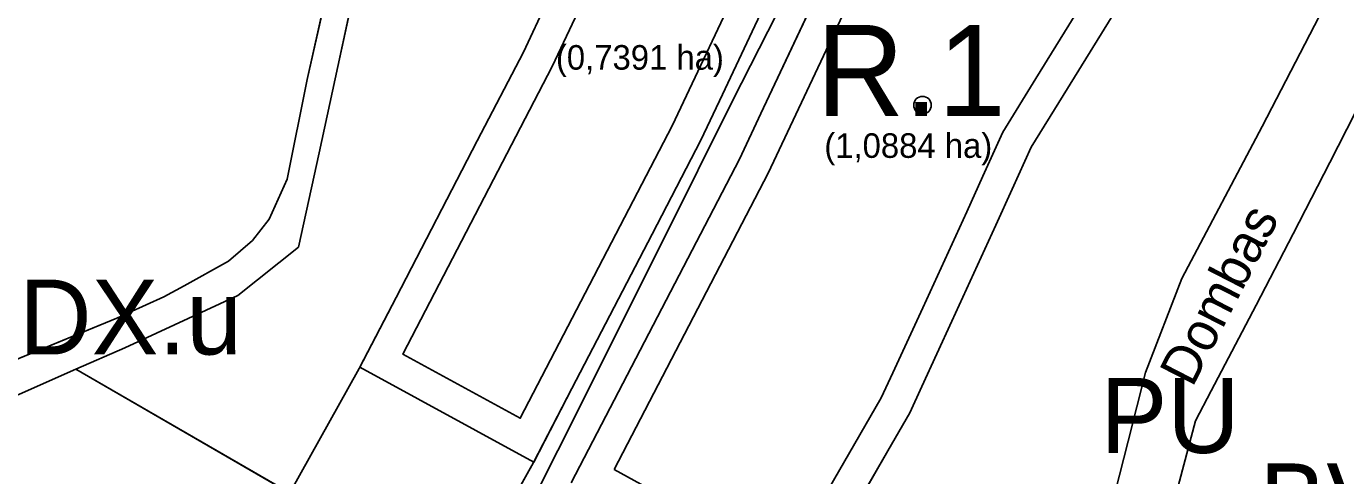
# Model space of a CAD drawing. Extents: x -555509 to -553005, y -1186756 to -1182560.
# Drawn here: x -554876.1 to -554629.7, y -1185321 to -1185237.1 of the extents above; entities that cross this region are included whole.
import ezdxf

# ---------------------------------------------------------------- set-up
doc = ezdxf.new("R2010")
doc.units = 0
for name, color, linetype in [('Level 15', 7, 'Continuous'), ('Level 26', 7, 'Continuous'), ('Level 29', 7, 'Continuous'), ('Level 36', 7, 'Continuous'), ('Level 4', 7, 'Continuous'), ('Level 46', 7, 'Continuous'), ('Level 52', 7, 'Continuous'), ('Level 56', 7, 'Continuous'), ('Level 57', 7, 'Continuous'), ('Level 59', 7, 'Continuous'), ('Level 6', 7, 'Continuous'), ('navrh_BV', 7, 'Continuous'), ('OBRYS_PLOCH', 7, 'Continuous'), ('rezerva_BV', 7, 'Continuous'), ('stav_AP', 7, 'Continuous'), ('stav_BV', 7, 'Continuous'), ('stav_PU', 7, 'Continuous'), ('stav_ZZ', 7, 'Continuous')]:
    doc.layers.add(name, color=color, linetype=linetype)

msp = doc.modelspace()

# ---------------------------------------------------------------- linework, layer by layer
at = {"layer": 'Level 15'}
for p, q in [((-554736.11, -1185228.65), (-554746.09, -1185249.82)), ((-554744.13, -1185250.86), (-554733.51, -1185230.02)), ((-554746.09, -1185249.82), (-554750.09, -1185258.31)), ((-554757.18, -1185276.99), (-554744.13, -1185250.86)), ((-554750.09, -1185258.31), (-554759.23, -1185275.9)), ((-554759.23, -1185275.9), (-554774.2, -1185304.73)), ((-554771.69, -1185306.03), (-554757.18, -1185276.99)), ((-554791.22, -1185344.83), (-554771.69, -1185306.03))]:
    msp.add_line(p, q, dxfattribs=at)
for points in [[(-554598.76, -1185166.79), (-554607.1, -1185184.92), (-554613.87, -1185198.73), (-554631.94, -1185230), (-554645.24, -1185255.79), (-554660.25, -1185284.19), (-554660.25, -1185284.19)], [(-554680.05, -1185391.93), (-554677.6, -1185383.35), (-554671.14, -1185360.64), (-554665.38, -1185339.39), (-554660.73, -1185322.02), (-554657.69, -1185310.75), (-554654.76, -1185305.13), (-554646.4, -1185289.14), (-554639.48, -1185275.83), (-554632.63, -1185262.48), (-554627.88, -1185253.22), (-554621, -1185239.68)], [(-554660.25, -1185284.19), (-554667.06, -1185301.73)], [(-554667.06, -1185301.73), (-554670.31, -1185314.54)], [(-554774.2, -1185304.73), (-554781.36, -1185318.51), (-554794.88, -1185342.72)], [(-554670.31, -1185314.54), (-554673.54, -1185327.25), (-554676.78, -1185340.05), (-554680, -1185352.72), (-554683.21, -1185365.38), (-554687.71, -1185383.13)]]:
    msp.add_lwpolyline(points, dxfattribs=at)
at = {"layer": 'Level 26'}
msp.add_line((-554817.98, -1185221.63), (-554823.63, -1185247), dxfattribs=at)
for points in [[(-554887.99, -1185310.44), (-554866.85, -1185301.12), (-554857.71, -1185297.09), (-554836.62, -1185287.33), (-554825.26, -1185278.31), (-554821.43, -1185260.7), (-554817.93, -1185244.58), (-554811.52, -1185215.05), (-554805.21, -1185192.12), (-554804.77, -1185189.6), (-554803.27, -1185184.93), (-554798.69, -1185167.93), (-554796.09, -1185156.74), (-554793.47, -1185148.48), (-554787.3, -1185127.39), (-554786.27, -1185123.73), (-554781.87, -1185108.14), (-554781.11, -1185105.46), (-554780.74, -1185090.36), (-554781.66, -1185076.22)], [(-554823.63, -1185247), (-554827.41, -1185265.63), (-554830.77, -1185273.06), (-554833.85, -1185277.07), (-554838.37, -1185280.92), (-554846.66, -1185285.51), (-554850.4, -1185287.59), (-554857.04, -1185290.6), (-554859.24, -1185291.6), (-554887.1, -1185303.03), (-554901.81, -1185309.08), (-554916.01, -1185314.9), (-554918.93, -1185316.1), (-554926.41, -1185318.46), (-554942.11, -1185323.84), (-554945.03, -1185324.82), (-554968.06, -1185330.5), (-554985.17, -1185335.34), (-555017.36, -1185344.44), (-555025.25, -1185346.9), (-555037.24, -1185350.65)]]:
    msp.add_lwpolyline(points, dxfattribs=at)
at = {"layer": 'Level 36'}
for p, q in [((-554791.87, -1185258.48), (-554807.06, -1185287.73)), ((-554807.06, -1185287.73), (-554813.94, -1185300.96)), ((-554813.94, -1185300.96), (-554826.92, -1185324.2))]:
    msp.add_line(p, q, dxfattribs=at)
msp.add_lwpolyline([(-554778.8, -1185232.44), (-554783.25, -1185241.89), (-554791.87, -1185258.48)], dxfattribs=at)
at = {"layer": 'Level 4'}
msp.add_circle((-554708.72, -1185251.8), 1.64, dxfattribs=at)
at = {"layer": 'Level 52'}
for points in [[(-554651.54, -1185198.32), (-554660.04, -1185213.75), (-554661.31, -1185215.81), (-554671.87, -1185232.89), (-554682.43, -1185249.97), (-554688.42, -1185259.67), (-554691.95, -1185267.5), (-554694.99, -1185274.23)], [(-554694.99, -1185274.23), (-554703.22, -1185292.14), (-554708.82, -1185304.31), (-554711.08, -1185309.23), (-554715.19, -1185316.37), (-554721.98, -1185328.15)]]:
    msp.add_lwpolyline(points, dxfattribs=at)
at = {"layer": 'Level 56'}
for p, q in [((-554813.94, -1185300.96), (-554826.92, -1185324.2)), ((-554813.83, -1185300.75), (-554813.94, -1185300.96)), ((-554781.34, -1185318.48), (-554813.83, -1185300.75))]:
    msp.add_line(p, q, dxfattribs=at)
msp.add_lwpolyline([(-554794.88, -1185342.72), (-554781.36, -1185318.51), (-554781.34, -1185318.48)], dxfattribs=at)
at = {"layer": 'Level 6'}
for points in [[(-554651.54, -1185198.32), (-554660.04, -1185213.75), (-554661.31, -1185215.81), (-554671.87, -1185232.89), (-554682.43, -1185249.97), (-554688.42, -1185259.67), (-554691.95, -1185267.5), (-554694.99, -1185274.23)], [(-554694.99, -1185274.23), (-554703.22, -1185292.14), (-554708.82, -1185304.31), (-554711.08, -1185309.23), (-554715.19, -1185316.37), (-554721.98, -1185328.15)]]:
    msp.add_lwpolyline(points, dxfattribs=at)
at = {"layer": 'navrh_BV'}
for p, q in [((-554813.94, -1185300.96), (-554826.92, -1185324.2)), ((-554813.94, -1185300.96), (-554826.92, -1185324.2)), ((-554813.83, -1185300.75), (-554813.94, -1185300.96)), ((-554813.83, -1185300.75), (-554813.94, -1185300.96)), ((-554781.34, -1185318.48), (-554813.83, -1185300.75)), ((-554781.34, -1185318.48), (-554813.83, -1185300.75)), ((-554794.88, -1185342.72), (-554781.36, -1185318.51)), ((-554794.88, -1185342.72), (-554781.36, -1185318.51)), ((-554781.36, -1185318.51), (-554781.34, -1185318.48)), ((-554781.36, -1185318.51), (-554781.34, -1185318.48))]:
    msp.add_line(p, q, dxfattribs=at)
at = {"layer": 'OBRYS_PLOCH'}
for p, q in [((-554811.52, -1185215.05), (-554817.93, -1185244.58)), ((-554817.98, -1185221.63), (-554823.63, -1185247)), ((-554736.11, -1185228.65), (-554746.09, -1185249.82)), ((-554671.87, -1185232.89), (-554682.43, -1185249.97)), ((-554817.93, -1185244.58), (-554821.43, -1185260.7)), ((-554682.43, -1185249.97), (-554688.42, -1185259.67)), ((-554742.92, -1185261.86), (-554738.91, -1185253.34)), ((-554821.43, -1185260.7), (-554825.26, -1185278.31)), ((-554807.06, -1185287.73), (-554791.87, -1185258.48)), ((-554688.42, -1185259.67), (-554691.95, -1185267.5)), ((-554774.32, -1185322.31), (-554742.92, -1185261.86)), ((-554691.95, -1185267.5), (-554694.99, -1185274.23)), ((-554759.23, -1185275.9), (-554774.2, -1185304.73)), ((-554825.26, -1185278.31), (-554836.62, -1185287.33)), ((-554836.62, -1185287.33), (-554857.71, -1185297.09)), ((-554813.94, -1185300.96), (-554807.06, -1185287.73)), ((-554857.71, -1185297.09), (-554866.85, -1185301.12)), ((-554866.85, -1185301.12), (-554826.92, -1185324.2)), ((-554826.92, -1185324.2), (-554813.94, -1185300.96)), ((-554813.94, -1185300.96), (-554826.92, -1185324.2)), ((-554813.83, -1185300.75), (-554813.94, -1185300.96)), ((-554781.34, -1185318.48), (-554813.83, -1185300.75)), ((-554774.2, -1185304.73), (-554781.36, -1185318.51)), ((-554781.36, -1185318.51), (-554794.88, -1185342.72)), ((-554794.88, -1185342.72), (-554781.36, -1185318.51)), ((-554781.36, -1185318.51), (-554781.34, -1185318.48))]:
    msp.add_line(p, q, dxfattribs=at)
for points in [[(-554887.99, -1185310.44), (-554866.85, -1185301.12), (-554857.71, -1185297.09), (-554836.62, -1185287.33), (-554825.26, -1185278.31), (-554821.43, -1185260.7), (-554817.93, -1185244.58), (-554811.52, -1185215.05), (-554805.21, -1185192.12), (-554804.77, -1185189.6), (-554803.27, -1185184.93), (-554798.69, -1185167.93), (-554796.09, -1185156.74), (-554793.47, -1185148.48), (-554787.3, -1185127.39), (-554786.27, -1185123.73), (-554781.87, -1185108.14), (-554781.11, -1185105.46), (-554780.74, -1185090.36), (-554781.66, -1185076.22)], [(-554738.91, -1185253.34), (-554709.98, -1185191.97), (-554688.49, -1185135.67)], [(-554887.1, -1185303.03), (-554859.24, -1185291.6), (-554857.04, -1185290.6), (-554850.4, -1185287.59), (-554846.66, -1185285.51), (-554838.37, -1185280.92), (-554833.85, -1185277.07), (-554830.77, -1185273.06), (-554827.41, -1185265.63), (-554823.63, -1185247), (-554817.98, -1185221.63), (-554810.95, -1185192.05), (-554810.27, -1185189.91), (-554835.6, -1185178.86), (-554845.02, -1185174.75), (-554857.62, -1185169.14), (-554867.48, -1185164.75), (-554870.22, -1185163.53), (-554877.3, -1185160.22)], [(-554660.25, -1185284.19), (-554645.24, -1185255.79), (-554631.94, -1185230), (-554613.87, -1185198.73), (-554607.1, -1185184.92), (-554598.76, -1185166.79)], [(-554791.87, -1185258.48), (-554783.25, -1185241.89), (-554778.8, -1185232.44)], [(-554588.35, -1185339.59), (-554594.02, -1185336.6), (-554595.16, -1185336), (-554581.44, -1185321.01), (-554582.54, -1185305.03), (-554583.52, -1185290.79), (-554585.87, -1185256.63), (-554586.41, -1185249.88), (-554586.6, -1185246.65), (-554587.16, -1185237.33), (-554607.25, -1185238.73), (-554621, -1185239.68), (-554627.88, -1185253.22), (-554632.63, -1185262.48), (-554639.48, -1185275.83), (-554646.4, -1185289.14), (-554654.76, -1185305.13), (-554657.69, -1185310.75), (-554660.73, -1185322.02), (-554665.38, -1185339.39), (-554671.14, -1185360.64), (-554677.6, -1185383.35), (-554680.05, -1185391.93)], [(-554823.63, -1185247), (-554827.41, -1185265.63), (-554830.77, -1185273.06), (-554833.85, -1185277.07), (-554838.37, -1185280.92), (-554846.66, -1185285.51), (-554850.4, -1185287.59), (-554857.04, -1185290.6), (-554859.24, -1185291.6), (-554887.1, -1185303.03), (-554901.81, -1185309.08), (-554916.01, -1185314.9), (-554918.93, -1185316.1), (-554926.41, -1185318.46), (-554942.11, -1185323.84), (-554945.03, -1185324.82), (-554968.06, -1185330.5), (-554985.17, -1185335.34), (-555017.36, -1185344.44), (-555025.25, -1185346.9), (-555037.24, -1185350.65)], [(-554746.09, -1185249.82), (-554750.09, -1185258.31), (-554759.23, -1185275.9)], [(-554694.99, -1185274.23), (-554703.22, -1185292.14), (-554708.82, -1185304.31), (-554711.08, -1185309.23), (-554715.19, -1185316.37), (-554721.98, -1185328.15), (-554728.42, -1185339.33), (-554731.79, -1185345.18), (-554734.88, -1185350.42), (-554742.18, -1185362.81), (-554744.55, -1185366.82), (-554747.05, -1185371.06), (-554752.81, -1185380.83), (-554760.45, -1185393.79), (-554768.14, -1185406.83), (-554772.69, -1185415.93)], [(-554761.09, -1185439.66), (-554755.74, -1185436.95), (-554734.36, -1185426.09), (-554706.82, -1185409.97), (-554695.2, -1185393.65), (-554687.71, -1185383.13), (-554683.21, -1185365.38), (-554680, -1185352.72), (-554676.78, -1185340.05), (-554673.54, -1185327.25), (-554670.31, -1185314.54), (-554667.06, -1185301.73), (-554660.25, -1185284.19)]]:
    msp.add_lwpolyline(points, dxfattribs=at)
at = {"layer": 'rezerva_BV'}
for p, q in [((-554709.98, -1185191.97), (-554738.91, -1185253.34)), ((-554709.98, -1185191.97), (-554738.91, -1185253.34)), ((-554746.09, -1185249.82), (-554736.11, -1185228.65)), ((-554746.09, -1185249.82), (-554736.11, -1185228.65)), ((-554778.8, -1185232.44), (-554783.25, -1185241.89)), ((-554778.8, -1185232.44), (-554783.25, -1185241.89)), ((-554682.43, -1185249.97), (-554671.87, -1185232.89)), ((-554682.43, -1185249.97), (-554671.87, -1185232.89)), ((-554783.25, -1185241.89), (-554791.87, -1185258.48)), ((-554783.25, -1185241.89), (-554791.87, -1185258.48)), ((-554687.53, -1185246.82), (-554693.73, -1185256.85)), ((-554688.42, -1185259.67), (-554682.43, -1185249.97)), ((-554688.42, -1185259.67), (-554682.43, -1185249.97)), ((-554738.91, -1185253.34), (-554742.92, -1185261.86)), ((-554738.91, -1185253.34), (-554742.92, -1185261.86)), ((-554693.73, -1185256.85), (-554697.42, -1185265.03)), ((-554791.87, -1185258.48), (-554807.06, -1185287.73)), ((-554791.87, -1185258.48), (-554807.06, -1185287.73)), ((-554691.95, -1185267.5), (-554688.42, -1185259.67)), ((-554691.95, -1185267.5), (-554688.42, -1185259.67)), ((-554742.92, -1185261.86), (-554774.32, -1185322.31)), ((-554742.92, -1185261.86), (-554774.32, -1185322.31)), ((-554697.42, -1185265.03), (-554700.45, -1185271.74)), ((-554694.99, -1185274.23), (-554691.95, -1185267.5)), ((-554694.99, -1185274.23), (-554691.95, -1185267.5)), ((-554700.45, -1185271.74), (-554708.67, -1185289.63)), ((-554703.22, -1185292.14), (-554694.99, -1185274.23)), ((-554703.22, -1185292.14), (-554694.99, -1185274.23)), ((-554774.2, -1185304.73), (-554759.23, -1185275.9)), ((-554774.2, -1185304.73), (-554759.23, -1185275.9)), ((-554807.06, -1185287.73), (-554813.83, -1185300.75)), ((-554807.06, -1185287.73), (-554813.83, -1185300.75)), ((-554708.67, -1185289.63), (-554714.27, -1185301.8)), ((-554708.82, -1185304.31), (-554703.22, -1185292.14)), ((-554708.82, -1185304.31), (-554703.22, -1185292.14)), ((-554813.83, -1185300.75), (-554781.34, -1185318.48)), ((-554813.83, -1185300.75), (-554781.34, -1185318.48)), ((-554714.27, -1185301.8), (-554716.42, -1185306.48)), ((-554781.34, -1185318.48), (-554774.2, -1185304.73)), ((-554781.34, -1185318.48), (-554774.2, -1185304.73)), ((-554711.08, -1185309.23), (-554708.82, -1185304.31)), ((-554711.08, -1185309.23), (-554708.82, -1185304.31)), ((-554716.42, -1185306.48), (-554720.39, -1185313.38)), ((-554715.19, -1185316.37), (-554711.08, -1185309.23)), ((-554715.19, -1185316.37), (-554711.08, -1185309.23)), ((-554721.98, -1185328.15), (-554715.19, -1185316.37)), ((-554721.98, -1185328.15), (-554715.19, -1185316.37))]:
    msp.add_line(p, q, dxfattribs=at)
for points in [[(-554755.47, -1185255.65), (-554783.85, -1185310.28), (-554805.8, -1185298.3), (-554777.88, -1185244.55), (-554763.45, -1185213.94), (-554747.57, -1185181.64), (-554725.82, -1185127.02), (-554704.58, -1185138.55), (-554722.87, -1185186.48), (-554728.14, -1185197.66), (-554738.8, -1185219.49), (-554741.6, -1185226.21), (-554755.47, -1185255.65)], [(-554655.3, -1185156.98), (-554639.41, -1185163.85), (-554647.14, -1185177.88), (-554656.8, -1185195.43), (-554665.22, -1185210.73), (-554666.42, -1185212.66), (-554687.53, -1185246.82)], [(-554766.29, -1185319.86), (-554737.54, -1185264.52), (-554704.46, -1185194.32)], [(-554759.23, -1185275.9), (-554750.09, -1185258.31), (-554746.09, -1185249.82)], [(-554759.23, -1185275.9), (-554750.09, -1185258.31), (-554746.09, -1185249.82)], [(-554720.39, -1185313.38), (-554727.18, -1185325.15), (-554733.62, -1185336.34), (-554734.07, -1185337.13), (-554736.41, -1185335.86)], [(-554753.81, -1185326.66), (-554762.58, -1185321.88), (-554766.29, -1185319.86)]]:
    msp.add_lwpolyline(points, dxfattribs=at)
at = {"layer": 'stav_AP'}
for p, q in [((-554823.63, -1185247), (-554817.98, -1185221.63)), ((-554838.37, -1185280.92), (-554833.85, -1185277.07)), ((-554846.66, -1185285.51), (-554838.37, -1185280.92)), ((-554857.04, -1185290.6), (-554850.4, -1185287.59)), ((-554850.4, -1185287.59), (-554846.66, -1185285.51)), ((-554887.1, -1185303.03), (-554859.24, -1185291.6)), ((-554859.24, -1185291.6), (-554857.04, -1185290.6)), ((-554794.88, -1185342.72), (-554866.85, -1185301.12))]:
    msp.add_line(p, q, dxfattribs=at)
for points in [[(-554833.85, -1185277.07), (-554830.77, -1185273.06), (-554827.41, -1185265.63), (-554823.63, -1185247)], [(-554866.85, -1185301.12), (-554887.99, -1185310.44), (-554902.78, -1185317.16), (-554916.95, -1185323.2), (-554921.41, -1185324.67)]]:
    msp.add_lwpolyline(points, dxfattribs=at)
at = {"layer": 'stav_BV'}
for p, q in [((-554671.87, -1185232.89), (-554682.43, -1185249.97)), ((-554682.43, -1185249.97), (-554688.42, -1185259.67)), ((-554688.42, -1185259.67), (-554691.95, -1185267.5)), ((-554691.95, -1185267.5), (-554694.99, -1185274.23))]:
    msp.add_line(p, q, dxfattribs=at)
for points in [[(-554660.25, -1185284.19), (-554645.24, -1185255.79), (-554631.94, -1185230), (-554613.87, -1185198.73), (-554607.1, -1185184.92), (-554598.76, -1185166.79)], [(-554588.35, -1185339.59), (-554594.02, -1185336.6), (-554595.16, -1185336), (-554581.44, -1185321.01), (-554582.54, -1185305.03), (-554583.52, -1185290.79), (-554585.87, -1185256.63), (-554586.41, -1185249.88), (-554586.6, -1185246.65), (-554587.16, -1185237.33), (-554607.25, -1185238.73), (-554621, -1185239.68), (-554627.88, -1185253.22), (-554632.63, -1185262.48), (-554639.48, -1185275.83), (-554646.4, -1185289.14), (-554654.76, -1185305.13), (-554657.69, -1185310.75), (-554660.73, -1185322.02), (-554665.38, -1185339.39), (-554671.14, -1185360.64), (-554677.6, -1185383.35), (-554680.05, -1185391.93)], [(-554694.99, -1185274.23), (-554703.22, -1185292.14), (-554708.82, -1185304.31), (-554711.08, -1185309.23), (-554715.19, -1185316.37), (-554721.98, -1185328.15), (-554728.42, -1185339.33), (-554731.79, -1185345.18), (-554734.88, -1185350.42), (-554742.18, -1185362.81), (-554744.55, -1185366.82), (-554747.05, -1185371.06), (-554752.81, -1185380.83), (-554760.45, -1185393.79), (-554768.14, -1185406.83), (-554772.69, -1185415.93)], [(-554761.09, -1185439.66), (-554755.74, -1185436.95), (-554734.36, -1185426.09), (-554706.82, -1185409.97), (-554695.2, -1185393.65), (-554687.71, -1185383.13), (-554683.21, -1185365.38), (-554680, -1185352.72), (-554676.78, -1185340.05), (-554673.54, -1185327.25), (-554670.31, -1185314.54), (-554667.06, -1185301.73), (-554660.25, -1185284.19)]]:
    msp.add_lwpolyline(points, dxfattribs=at)
at = {"layer": 'stav_PU'}
for p, q in [((-554736.11, -1185228.65), (-554746.09, -1185249.82)), ((-554746.09, -1185249.82), (-554750.09, -1185258.31)), ((-554742.92, -1185261.86), (-554738.91, -1185253.34)), ((-554750.09, -1185258.31), (-554759.23, -1185275.9)), ((-554774.32, -1185322.31), (-554742.92, -1185261.86)), ((-554759.23, -1185275.9), (-554774.2, -1185304.73)), ((-554771.69, -1185306.03), (-554757.18, -1185276.99)), ((-554757.18, -1185276.99), (-554764, -1185290.64)), ((-554660.25, -1185284.19), (-554667.06, -1185301.73)), ((-554764, -1185290.64), (-554771.69, -1185306.03)), ((-554667.06, -1185301.73), (-554670.31, -1185314.54)), ((-554774.2, -1185304.73), (-554781.36, -1185318.51)), ((-554781.36, -1185318.51), (-554794.88, -1185342.72))]:
    msp.add_line(p, q, dxfattribs=at)
for points in [[(-554738.91, -1185253.34), (-554709.98, -1185191.97), (-554688.49, -1185135.67)], [(-554598.76, -1185166.79), (-554607.1, -1185184.92), (-554613.87, -1185198.73), (-554631.94, -1185230), (-554645.24, -1185255.79), (-554660.25, -1185284.19)], [(-554680.05, -1185391.93), (-554677.6, -1185383.35), (-554671.14, -1185360.64), (-554665.38, -1185339.39), (-554660.73, -1185322.02), (-554657.69, -1185310.75), (-554654.76, -1185305.13), (-554646.4, -1185289.14), (-554639.48, -1185275.83), (-554632.63, -1185262.48), (-554627.88, -1185253.22), (-554621, -1185239.68)], [(-554670.31, -1185314.54), (-554673.54, -1185327.25), (-554676.78, -1185340.05), (-554680, -1185352.72), (-554683.21, -1185365.38), (-554687.71, -1185383.13)]]:
    msp.add_lwpolyline(points, dxfattribs=at)
at = {"layer": 'stav_ZZ'}
for p, q in [((-554811.52, -1185215.05), (-554817.93, -1185244.58)), ((-554746.09, -1185249.82), (-554736.11, -1185228.65)), ((-554682.43, -1185249.97), (-554671.87, -1185232.89)), ((-554817.93, -1185244.58), (-554821.43, -1185260.7)), ((-554750.09, -1185258.31), (-554746.09, -1185249.82)), ((-554688.42, -1185259.67), (-554682.43, -1185249.97)), ((-554738.91, -1185253.34), (-554742.92, -1185261.86)), ((-554821.43, -1185260.7), (-554825.26, -1185278.31)), ((-554807.06, -1185287.73), (-554791.87, -1185258.48)), ((-554791.87, -1185258.48), (-554807.06, -1185287.73)), ((-554759.23, -1185275.9), (-554750.09, -1185258.31)), ((-554691.95, -1185267.5), (-554688.42, -1185259.67)), ((-554742.92, -1185261.86), (-554774.32, -1185322.31)), ((-554694.99, -1185274.23), (-554691.95, -1185267.5)), ((-554703.22, -1185292.14), (-554694.99, -1185274.23)), ((-554774.2, -1185304.73), (-554759.23, -1185275.9)), ((-554813.94, -1185300.96), (-554807.06, -1185287.73)), ((-554807.06, -1185287.73), (-554813.83, -1185300.75)), ((-554708.82, -1185304.31), (-554703.22, -1185292.14)), ((-554857.71, -1185297.09), (-554866.85, -1185301.12)), ((-554866.85, -1185301.12), (-554826.92, -1185324.2)), ((-554826.92, -1185324.2), (-554813.94, -1185300.96)), ((-554813.83, -1185300.75), (-554781.34, -1185318.48)), ((-554781.34, -1185318.48), (-554774.2, -1185304.73)), ((-554711.08, -1185309.23), (-554708.82, -1185304.31)), ((-554715.19, -1185316.37), (-554711.08, -1185309.23))]:
    msp.add_line(p, q, dxfattribs=at)
for points in [[(-554688.49, -1185135.67), (-554709.98, -1185191.97), (-554738.91, -1185253.34)], [(-554791.87, -1185258.48), (-554783.25, -1185241.89), (-554778.8, -1185232.44)], [(-554778.8, -1185232.44), (-554783.25, -1185241.89), (-554791.87, -1185258.48)], [(-554825.26, -1185278.31), (-554836.62, -1185287.33), (-554857.71, -1185297.09)], [(-554731.79, -1185345.18), (-554728.42, -1185339.33), (-554721.98, -1185328.15), (-554715.19, -1185316.37)]]:
    msp.add_lwpolyline(points, dxfattribs=at)

# ---------------------------------------------------------------- texts
at = {"layer": 'Level 29'}
for s, p in [('(0,7391 ha)', (-554777.19, -1185245.17)), ('(1,0884 ha)', (-554727.06, -1185261.64))]:
    msp.add_text(s, height=4.5875, dxfattribs=at).set_placement(p)
at = {"layer": 'Level 46'}
msp.add_text('R.1', height=17, dxfattribs=at).set_placement((-554728.55, -1185253.82))
at = {"layer": 'Level 57'}
msp.add_text('Dombas', height=7.174, rotation=62.8233, dxfattribs=at).set_placement((-554658.31, -1185304.68))
at = {"layer": 'Level 59'}
for s, p in [('DX.u', (-554877.44, -1185298.36)), ('PU', (-554675.46, -1185316.75)), ('BV', (-554645.75, -1185332.7))]:
    msp.add_text(s, height=14, dxfattribs=at).set_placement(p)

doc.saveas('drawing.dxf')
